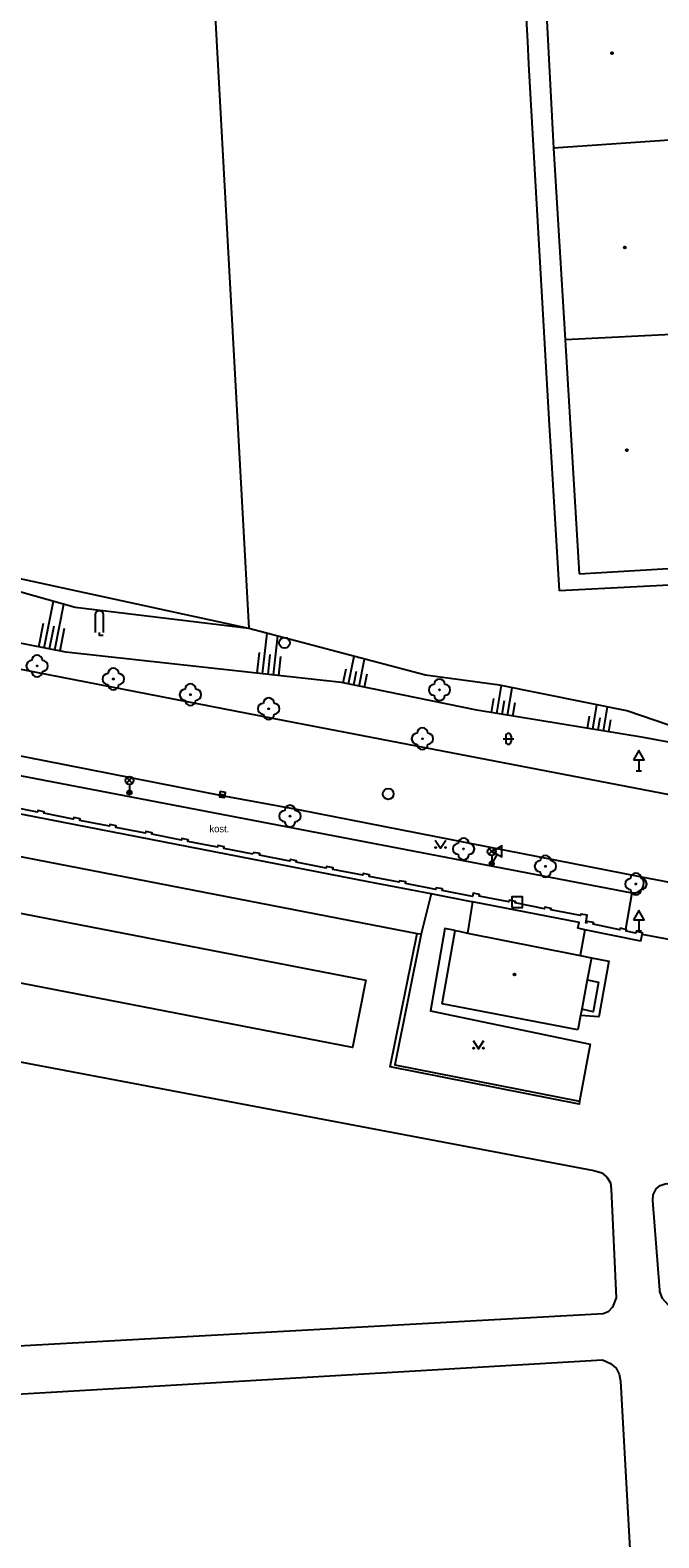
# Model space of a CAD drawing. Extents: x -599951 to -598963, y -1164095 to -1162939.
# Drawn here: x -599492.5 to -599434.3, y -1163192.8 to -1163053.4 of the extents above; entities that cross this region are included whole.
import ezdxf

# ---------------------------------------------------------------- set-up
doc = ezdxf.new("R2010")
doc.units = 0
for name, color, linetype in [('Level 10', 7, 'Continuous'), ('Level 11', 7, 'Continuous'), ('Level 14', 7, 'Continuous'), ('Level 15', 7, 'Continuous'), ('Level 22', 7, 'Continuous'), ('Level 26', 7, 'Continuous'), ('Level 27', 7, 'Continuous'), ('Level 33', 7, 'Continuous'), ('Level 34', 7, 'Continuous'), ('Level 36', 7, 'Continuous'), ('Level 39', 7, 'Continuous'), ('Level 40', 7, 'Continuous'), ('Level 5', 7, 'Continuous'), ('Level 54', 7, 'Continuous'), ('Level 7', 7, 'Continuous'), ('Level 8', 7, 'Continuous')]:
    doc.layers.add(name, color=color, linetype=linetype)

msp = doc.modelspace()

# ---------------------------------------------------------------- linework, layer by layer
at = {"layer": 'Level 10'}
for points in [[(-599575.76, -1163096.42), (-599468.94, -1163117.19), (-599432.56, -1163124.21)], [(-599435.87, -1163131.7), (-599467.64, -1163125.46), (-599474.7, -1163124.18), (-599491.13, -1163120.93), (-599510.23, -1163117.2), (-599530.53, -1163113.28), (-599545.61, -1163110.31), (-599561.46, -1163107.25), (-599577.11, -1163104.2)], [(-599427.48, -1163133.31), (-599435.87, -1163131.7)]]:
    msp.add_lwpolyline(points, dxfattribs=at)
at = {"layer": 'Level 11'}
for points in [[(-599479.08, -1162984.23), (-599472.24, -1163108.69)], [(-599446.44, -1163054.4), (-599448.4, -1163019.93)], [(-599446.32, -1163056.5), (-599446.44, -1163054.4)], [(-599444.43, -1163089.89), (-599446.32, -1163056.5)], [(-599472.24, -1163108.69), (-599560.57, -1163089.51)], [(-599444.28, -1163092.34), (-599444.43, -1163089.89)], [(-599654.24, -1163091.04), (-599560.56, -1163109.31), (-599529.97, -1163115.28), (-599436.82, -1163133.13)], [(-599443.51, -1163105.2), (-599444.28, -1163092.34)], [(-599424.37, -1163104.22), (-599443.51, -1163105.2)], [(-599501.34, -1163128.23), (-599456.66, -1163136.89)], [(-599436.82, -1163133.13), (-599436.64, -1163133.15), (-599436.45, -1163133.13), (-599436.28, -1163133.08), (-599436.12, -1163133), (-599435.97, -1163132.88), (-599435.86, -1163132.74), (-599435.77, -1163132.58), (-599435.72, -1163132.4), (-599435.7, -1163132.22), (-599435.72, -1163132.04), (-599435.78, -1163131.86), (-599435.87, -1163131.7)], [(-599455.38, -1163133.25), (-599456.31, -1163136.94)], [(-599436.82, -1163133.13), (-599437.38, -1163136.52)], [(-599499.13, -1163133.9), (-599461.43, -1163141.21), (-599462.64, -1163147.45), (-599500.35, -1163140.14), (-599499.13, -1163133.9)], [(-599451.55, -1163133.99), (-599452.02, -1163136.87)], [(-599453.14, -1163136.64), (-599454.1, -1163136.45), (-599455.43, -1163144.06), (-599440.65, -1163147.15), (-599441.66, -1163152.4)], [(-599441.16, -1163136.55), (-599441.6, -1163138.94)], [(-599440.54, -1163139.15), (-599438.92, -1163139.47), (-599439.87, -1163144.6), (-599441.55, -1163144.49)], [(-599440.93, -1163141.2), (-599439.9, -1163141.4), (-599440.38, -1163144.16), (-599441.44, -1163143.89)], [(-599499.14, -1163147.68), (-599440.31, -1163158.82), (-599439.57, -1163159.05), (-599439.13, -1163159.43), (-599438.79, -1163159.96), (-599438.72, -1163160.56), (-599438.26, -1163170.61), (-599438.58, -1163171.46), (-599439.01, -1163171.88), (-599439.46, -1163172.08), (-599498.04, -1163175.3), (-599498.59, -1163175.16), (-599499.19, -1163174.73), (-599499.6, -1163173.85), (-599501.08, -1163150.03), (-599500.94, -1163149.12), (-599500.47, -1163148.36), (-599499.9, -1163147.92), (-599499.3, -1163147.71), (-599499.14, -1163147.68)], [(-599433.64, -1163160.02), (-599399.13, -1163166.98), (-599398.74, -1163167.6), (-599398.67, -1163168.14), (-599398.85, -1163168.83), (-599399.29, -1163169.37), (-599431.94, -1163171.66), (-599432.73, -1163171.6), (-599433.44, -1163171.24), (-599433.96, -1163170.65), (-599434.21, -1163170.02), (-599434.23, -1163169.88), (-599434.86, -1163161.61), (-599434.84, -1163161.07), (-599434.54, -1163160.53), (-599434.18, -1163160.21), (-599433.64, -1163160.02)], [(-599481.04, -1163178.76), (-599439.52, -1163176.34)], [(-599439.52, -1163176.34), (-599438.77, -1163176.66), (-599438.27, -1163177.1), (-599437.98, -1163177.66), (-599437.84, -1163178.31), (-599437.2, -1163189.93)]]:
    msp.add_lwpolyline(points, dxfattribs=at)
at = {"layer": 'Level 14'}
for points in [[(-599472.24, -1163108.69), (-599488.31, -1163106.74), (-599506.04, -1163101.75), (-599543.68, -1163094.08), (-599554.26, -1163088.1), (-599556.17, -1163084.65), (-599555.79, -1163080.39)], [(-599423.27, -1163121.1), (-599435.72, -1163118.79), (-599451.15, -1163116.24), (-599463.66, -1163113.69), (-599489.16, -1163110.88), (-599508.36, -1163107.11), (-599527.75, -1163103.16), (-599545.37, -1163099.59), (-599551.42, -1163096.73)], [(-599423.27, -1163121.1), (-599437.28, -1163116.31), (-599449.05, -1163113.93), (-599455.91, -1163113), (-599472.24, -1163108.69)]]:
    msp.add_lwpolyline(points, dxfattribs=at)
at = {"layer": 'Level 15'}
for points in [[(-599491.17, -1163110.49), (-599490.32, -1163106.17)], [(-599490.18, -1163110.68), (-599489.35, -1163106.45)], [(-599491.66, -1163110.39), (-599491.23, -1163108.21)], [(-599490.68, -1163110.58), (-599490.26, -1163108.45)], [(-599489.69, -1163110.77), (-599489.28, -1163108.68)], [(-599470.96, -1163112.88), (-599470.55, -1163109.14)], [(-599469.97, -1163112.99), (-599469.57, -1163109.39)], [(-599471.46, -1163112.83), (-599471.25, -1163110.92)], [(-599470.46, -1163112.94), (-599470.26, -1163111.1)], [(-599469.47, -1163113.05), (-599469.28, -1163111.29)], [(-599463.02, -1163113.82), (-599462.5, -1163111.26)], [(-599462.04, -1163114.02), (-599461.53, -1163111.52)], [(-599463.51, -1163113.72), (-599463.24, -1163112.43)], [(-599462.53, -1163113.92), (-599462.27, -1163112.65)], [(-599461.55, -1163114.12), (-599461.3, -1163112.88)], [(-599449.29, -1163116.55), (-599448.86, -1163113.97)], [(-599448.3, -1163116.71), (-599447.88, -1163114.17)], [(-599449.78, -1163116.47), (-599449.57, -1163115.18)], [(-599448.79, -1163116.63), (-599448.58, -1163115.35)], [(-599447.81, -1163116.79), (-599447.6, -1163115.53)], [(-599440.41, -1163118.01), (-599440.03, -1163115.75)], [(-599439.42, -1163118.18), (-599439.05, -1163115.95)], [(-599440.9, -1163117.93), (-599440.71, -1163116.79)], [(-599439.92, -1163118.1), (-599439.73, -1163116.97)], [(-599438.93, -1163118.26), (-599438.75, -1163117.15)]]:
    msp.add_lwpolyline(points, dxfattribs=at)
at = {"layer": 'Level 22'}
for centre in [(-599491.83, -1163112.16), (-599484.77, -1163113.37), (-599477.64, -1163114.82), (-599454.6, -1163114.37), (-599470.4, -1163116.12), (-599456.18, -1163118.89), (-599468.43, -1163126.05), (-599452.37, -1163129.08), (-599444.8, -1163130.69), (-599436.43, -1163132.33)]:
    msp.add_circle(centre, 0.05, dxfattribs=at)
for centre, start, end in [((-599492.33, -1163112.16), 90, 270), ((-599491.83, -1163111.66), 0, 180), ((-599491.33, -1163112.16), 270, 90), ((-599484.77, -1163112.87), 0, 180), ((-599491.83, -1163112.66), 180, 0), ((-599485.27, -1163113.37), 90, 270), ((-599484.27, -1163113.37), 270, 90), ((-599454.6, -1163113.87), 0, 180), ((-599484.77, -1163113.87), 180, 0), ((-599478.14, -1163114.82), 90, 270), ((-599477.64, -1163114.32), 0, 180), ((-599477.14, -1163114.82), 270, 90), ((-599470.4, -1163115.62), 0, 180), ((-599455.1, -1163114.37), 90, 270), ((-599454.6, -1163114.87), 180, 0), ((-599454.1, -1163114.37), 270, 90), ((-599477.64, -1163115.32), 180, 0), ((-599470.9, -1163116.12), 90, 270), ((-599469.9, -1163116.12), 270, 90), ((-599470.4, -1163116.62), 180, 0), ((-599456.18, -1163118.39), 0, 180), ((-599456.68, -1163118.89), 90, 270), ((-599455.68, -1163118.89), 270, 90), ((-599456.18, -1163119.39), 180, 0), ((-599468.93, -1163126.05), 90, 270), ((-599468.43, -1163125.55), 0, 180), ((-599467.93, -1163126.05), 270, 90), ((-599468.43, -1163126.55), 180, 0), ((-599452.87, -1163129.08), 90, 270), ((-599452.37, -1163128.58), 0, 180), ((-599451.87, -1163129.08), 270, 90), ((-599452.37, -1163129.58), 180, 0), ((-599445.3, -1163130.69), 90, 270), ((-599444.8, -1163130.19), 0, 180), ((-599444.3, -1163130.69), 270, 90), ((-599444.8, -1163131.19), 180, 0), ((-599436.93, -1163132.33), 90, 270), ((-599436.43, -1163131.83), 0, 180), ((-599435.93, -1163132.33), 270, 90), ((-599436.43, -1163132.83), 180, 0)]:
    msp.add_arc(centre, 0.5, start, end, dxfattribs=at)
at = {"layer": 'Level 26'}
msp.add_lwpolyline([(-599447.91, -1163134.5), (-599446.91, -1163134.5), (-599446.91, -1163133.5), (-599447.91, -1163133.5)], close=True, dxfattribs=at)
at = {"layer": 'Level 27'}
msp.add_line((-599474.93, -1163124.01), (-599474.43, -1163124.09), dxfattribs=at)
msp.add_lwpolyline([(-599474.97, -1163124.25), (-599474.48, -1163124.34), (-599474.39, -1163123.85), (-599474.88, -1163123.76)], close=True, dxfattribs=at)
for centre in [(-599468.94, -1163110.02), (-599459.34, -1163124)]:
    msp.add_circle(centre, 0.5, dxfattribs=at)
at = {"layer": 'Level 33'}
for p, q in [((-599483.55, -1163123.01), (-599483.02, -1163122.48)), ((-599483.55, -1163122.48), (-599483.02, -1163123.01)), ((-599483.28, -1163123.12), (-599483.28, -1163123.87)), ((-599450.03, -1163129.58), (-599449.5, -1163129.05)), ((-599450.03, -1163129.05), (-599449.5, -1163129.58)), ((-599449.77, -1163129.69), (-599449.77, -1163130.44))]:
    msp.add_line(p, q, dxfattribs=at)
for centre, radius in [((-599483.28, -1163122.75), 0.375), ((-599483.28, -1163123.87), 0.2), ((-599483.28, -1163123.87), 0.145), ((-599483.28, -1163123.87), 0.0876), ((-599449.77, -1163129.32), 0.375), ((-599449.77, -1163130.44), 0.2), ((-599449.77, -1163130.44), 0.145), ((-599449.77, -1163130.44), 0.0876)]:
    msp.add_circle(centre, radius, dxfattribs=at)
at = {"layer": 'Level 34'}
for p, q in [((-599436.41, -1163121.87), (-599435.91, -1163121.87)), ((-599436.16, -1163120.85), (-599436.16, -1163121.87)), ((-599449.99, -1163130.32), (-599449.55, -1163130.56)), ((-599449.26, -1163129.56), (-599449.77, -1163130.44)), ((-599436.16, -1163135.65), (-599436.16, -1163136.67)), ((-599436.41, -1163136.67), (-599435.91, -1163136.67))]:
    msp.add_line(p, q, dxfattribs=at)
for points in [[(-599436.66, -1163120.85), (-599435.66, -1163120.85), (-599436.16, -1163119.99)], [(-599449.7, -1163129.31), (-599448.83, -1163129.81), (-599448.83, -1163128.81)], [(-599436.66, -1163135.65), (-599435.66, -1163135.65), (-599436.16, -1163134.79)]]:
    msp.add_lwpolyline(points, close=True, dxfattribs=at)
at = {"layer": 'Level 36'}
for p, q in [((-599486.45, -1163107.43), (-599486.45, -1163109.06)), ((-599485.7, -1163107.43), (-599485.7, -1163109.06)), ((-599448.72, -1163118.9), (-599447.72, -1163118.9)), ((-599448.47, -1163118.65), (-599448.47, -1163119.15)), ((-599447.97, -1163118.65), (-599447.97, -1163119.15))]:
    msp.add_line(p, q, dxfattribs=at)
for points in [[(-599486.07, -1163109.06), (-599486.07, -1163109.31), (-599485.7, -1163109.31)], [(-599455, -1163128.26), (-599454.5, -1163129.01), (-599454, -1163128.26)], [(-599451.49, -1163146.81), (-599450.99, -1163147.56), (-599450.49, -1163146.81)]]:
    msp.add_lwpolyline(points, dxfattribs=at)
for centre in [(-599454.95, -1163128.96), (-599454.05, -1163128.96), (-599451.44, -1163147.51), (-599450.54, -1163147.51)]:
    msp.add_circle(centre, 0.05, dxfattribs=at)
for centre, radius, start, end in [((-599486.07, -1163107.43), 0.375, 0, 180), ((-599448.22, -1163118.65), 0.25, 0, 180), ((-599448.22, -1163119.15), 0.25, 180, 0)]:
    msp.add_arc(centre, radius, start, end, dxfattribs=at)
at = {"layer": 'Level 39'}
for centre, radius in [((-599438.64, -1163055.48), 0.09), ((-599438.64, -1163055.48), 0.0398), ((-599437.46, -1163073.45), 0.09), ((-599437.46, -1163073.45), 0.0398), ((-599437.26, -1163092.21), 0.09), ((-599437.26, -1163092.21), 0.0398), ((-599447.66, -1163140.69), 0.09), ((-599447.66, -1163140.69), 0.0398)]:
    msp.add_circle(centre, radius, dxfattribs=at)
at = {"layer": 'Level 5'}
for points in [[(-599445.01, -1163045.98), (-599444.04, -1163064.28)], [(-599432.88, -1163063.51), (-599444.04, -1163064.28)], [(-599444.04, -1163064.28), (-599442.98, -1163082.01)], [(-599431.89, -1163081.43), (-599442.98, -1163082.01)], [(-599442.98, -1163082.01), (-599441.69, -1163103.65)], [(-599441.69, -1163103.65), (-599430.87, -1163102.98)], [(-599454.34, -1163143.41), (-599453.14, -1163136.64)], [(-599453.14, -1163136.64), (-599452.78, -1163136.7)], [(-599452.78, -1163136.7), (-599452.02, -1163136.87)], [(-599452.02, -1163136.87), (-599442.19, -1163138.82)], [(-599442.19, -1163138.82), (-599441.6, -1163138.94)], [(-599441.6, -1163138.94), (-599440.54, -1163139.15)], [(-599440.54, -1163139.15), (-599440.93, -1163141.2)], [(-599440.93, -1163141.2), (-599441.44, -1163143.89)], [(-599441.8, -1163145.81), (-599454.34, -1163143.41)], [(-599441.44, -1163143.89), (-599441.55, -1163144.49)], [(-599441.55, -1163144.49), (-599441.8, -1163145.81)]]:
    msp.add_lwpolyline(points, dxfattribs=at)
at = {"layer": 'Level 54'}
for points in [[(-599497.95, -1163179.75), (-599481.04, -1163178.76)], [(-599437.2, -1163189.93), (-599434.63, -1163236.8)]]:
    msp.add_lwpolyline(points, dxfattribs=at)
at = {"layer": 'Level 7'}
for points in [[(-599455.38, -1163133.25), (-599461.2, -1163132.12), (-599481.31, -1163128.22), (-599506.03, -1163123.39)], [(-599471.83, -1163129.56), (-599474.56, -1163129.03), (-599474.53, -1163128.88), (-599475.12, -1163128.76), (-599475.15, -1163128.91), (-599477.89, -1163128.38), (-599477.86, -1163128.23), (-599478.45, -1163128.12), (-599478.48, -1163128.26), (-599481.22, -1163127.73), (-599481.19, -1163127.59), (-599481.78, -1163127.47), (-599481.8, -1163127.62), (-599484.54, -1163127.09), (-599484.51, -1163126.94), (-599485.1, -1163126.82), (-599485.13, -1163126.97), (-599487.87, -1163126.44), (-599487.84, -1163126.29), (-599488.43, -1163126.18), (-599488.48, -1163126.32), (-599491.2, -1163125.79), (-599491.17, -1163125.64), (-599491.76, -1163125.53), (-599491.79, -1163125.68), (-599494.23, -1163125.2)], [(-599437.38, -1163136.52), (-599437.9, -1163136.41), (-599437.93, -1163136.56), (-599440.39, -1163136.05), (-599440.36, -1163135.9), (-599440.94, -1163135.78), (-599440.97, -1163135.93), (-599441.07, -1163135.91), (-599440.94, -1163135.22), (-599441.53, -1163135.11), (-599441.56, -1163135.25), (-599444.29, -1163134.72), (-599444.26, -1163134.58), (-599444.85, -1163134.46), (-599444.88, -1163134.61), (-599447.61, -1163134.08), (-599447.58, -1163133.94), (-599448.17, -1163133.82), (-599448.2, -1163133.97), (-599450.93, -1163133.44), (-599450.9, -1163133.29), (-599451.49, -1163133.18), (-599451.55, -1163133.48), (-599454.35, -1163132.93), (-599454.32, -1163132.78), (-599454.91, -1163132.67), (-599454.94, -1163132.82), (-599457.73, -1163132.28), (-599457.7, -1163132.13), (-599458.29, -1163132.02), (-599458.32, -1163132.17), (-599461.11, -1163131.63), (-599461.08, -1163131.48), (-599461.67, -1163131.37), (-599461.69, -1163131.51), (-599464.48, -1163130.97), (-599464.45, -1163130.83), (-599465.04, -1163130.71), (-599465.07, -1163130.86), (-599467.86, -1163130.32), (-599467.83, -1163130.17), (-599468.42, -1163130.06), (-599468.45, -1163130.21), (-599471.24, -1163129.67), (-599471.21, -1163129.52), (-599471.8, -1163129.41), (-599471.83, -1163129.56)], [(-599451.55, -1163133.99), (-599451.64, -1163133.97), (-599455.38, -1163133.25)], [(-599441.16, -1163136.55), (-599441.79, -1163136.42), (-599441.68, -1163135.89), (-599451.55, -1163133.99)], [(-599441.66, -1163152.4), (-599441.67, -1163152.69), (-599459.17, -1163149.23), (-599456.66, -1163136.89)], [(-599456.31, -1163136.94), (-599458.73, -1163149.04), (-599441.66, -1163152.4)], [(-599456.66, -1163136.89), (-599456.31, -1163136.94)], [(-599435.97, -1163137.62), (-599441.16, -1163136.55)], [(-599435.84, -1163136.99), (-599435.81, -1163136.84), (-599436.4, -1163136.72), (-599436.43, -1163136.87), (-599437.34, -1163136.68), (-599437.31, -1163136.53), (-599437.38, -1163136.52)], [(-599435.97, -1163137.62), (-599435.84, -1163136.99)]]:
    msp.add_lwpolyline(points, dxfattribs=at)
at = {"layer": 'Level 8'}
msp.add_lwpolyline([(-599431.52, -1163137.8), (-599435.84, -1163136.99)], dxfattribs=at)

# ---------------------------------------------------------------- texts
at = {"layer": 'Level 40'}
msp.add_text('kost.', height=0.65, dxfattribs=at).set_placement((-599475.88, -1163127.54))

doc.saveas('drawing.dxf')
